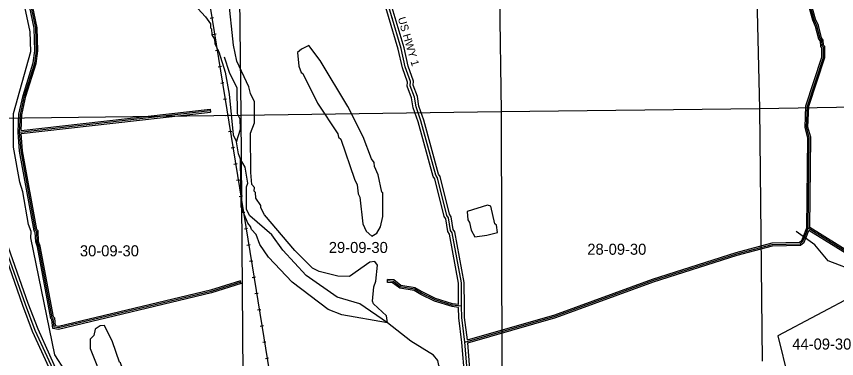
# Model space of a CAD drawing. Extents: x 418523 to 616617, y 1878279 to 2196743.
# Drawn here: x 553602 to 570344, y 1945489 to 1952469 of the extents above; entities that cross this region are included whole.
import ezdxf

# ---------------------------------------------------------------- set-up
doc = ezdxf.new("R2010")
doc.units = 0
for name, color, linetype in [('Level 1', 7, 'Continuous'), ('Level 13', 7, 'Continuous'), ('Level 14', 7, 'Continuous'), ('Level 19', 7, 'Continuous'), ('Level 2', 7, 'Continuous'), ('Level 31', 7, 'Continuous'), ('Level 32', 7, 'Continuous'), ('Level 34', 7, 'Continuous'), ('Level 37', 7, 'Continuous'), ('Level 5', 7, 'Continuous'), ('Level 7', 7, 'Continuous')]:
    doc.layers.add(name, color=color, linetype=linetype)

msp = doc.modelspace()

# ---------------------------------------------------------------- linework, layer by layer
at = {"layer": 'Level 1'}
for p, q in [((563413.668, 1955811.287), (563498.761, 1950526.305)), ((568644.303, 1955869.218), (568769.441, 1950592.162)), ((558122.982, 1955755.473), (558186.036, 1950452.524)), ((563498.761, 1950526.305), (568769.441, 1950592.162)), ((568769.441, 1950592.162), (573637.791, 1950674.806)), ((568769.441, 1950592.162), (568822.676, 1945437.311)), ((552971.413, 1950392.562), (558186.036, 1950452.524)), ((558186.036, 1950452.524), (563498.761, 1950526.305)), ((558186.036, 1950452.524), (558223.052, 1945139.621)), ((563498.761, 1950526.305), (563513.797, 1945243.459)), ((571579.462, 1947242.951), (569145.641, 1945954.963)), ((569145.641, 1945954.963), (571104.953, 1938088.985))]:
    msp.add_line(p, q, dxfattribs=at)
at = {"layer": 'Level 13'}
msp.add_line((562821.593, 1944999.369), (562756.996, 1945825.017), dxfattribs=at)
for points in [[(562689.623, 1946556.488), (562685.435, 1947033.971), (562496.226, 1948051.581), (562463.011, 1948101.485), (562422.072, 1948360.144), (562388.86, 1948410.412), (562199.028, 1949177.834), (562165.816, 1949227.738), (561860.66, 1950337.288), (561761.371, 1950621.189), (561728.546, 1950821.281), (561637.386, 1951054.979), (561645.854, 1951138.233), (561538.356, 1951438.521), (561456.135, 1951814.019), (561059.554, 1953157.276)], [(554472.45, 1945001.799), (553987.946, 1946065.361), (553789.032, 1946591.025), (553292.812, 1947992.826), (553284.471, 1948076.125), (553259.751, 1948092.921), (553243.201, 1948192.972), (553185.056, 1948293.139), (553143.949, 1948468.533), (553118.911, 1948485.331), (553011.661, 1948852.191), (552978.461, 1948902.468), (552912.389, 1949119.39), (552564.836, 1950070.586), (552399.28, 1950587.8), (552316.54, 1950746.585), (552184.116, 1951188.796), (552076.625, 1951464.019), (552043.066, 1951610.666)], [(562756.996, 1945825.017), (562691.579, 1946325.566), (562689.623, 1946556.488)]]:
    msp.add_lwpolyline(points, dxfattribs=at)
at = {"layer": 'Level 14'}
for p, q in [((562759.357, 1945025.605), (562697.3, 1945818.785)), ((562881.308, 1945005.39), (562818.249, 1945811.365))]:
    msp.add_line(p, q, dxfattribs=at)
for points in [[(562629.292, 1946593.916), (562625.482, 1947028.18), (562439.477, 1948028.55), (562405.797, 1948079.155), (562364.842, 1948337.919), (562333.097, 1948385.966), (562143.291, 1949153.286), (562110.521, 1949202.526), (561803.348, 1950319.407), (561703.008, 1950606.316), (561670.356, 1950805.348), (561576.228, 1951046.654), (561584.786, 1951130.796), (561480.567, 1951421.924), (561397.981, 1951799.088), (561001.794, 1953141.016)], [(562749.622, 1946557.015), (562745.388, 1947039.763), (562552.973, 1948074.611), (562520.226, 1948123.814), (562479.303, 1948382.37), (562444.622, 1948434.86), (562254.766, 1949202.381), (562221.111, 1949252.951), (561917.972, 1950355.168), (561819.735, 1950636.062), (561786.735, 1950837.214), (561698.544, 1951063.303), (561706.921, 1951145.671), (561596.145, 1951455.116), (561514.288, 1951828.951), (561130.681, 1953128.266)], [(554419.556, 1944973.172), (553932.526, 1946042.281), (553732.686, 1946570.393), (553233.831, 1947979.636), (553227.561, 1948042.251), (553204.752, 1948057.75), (553185.796, 1948172.346), (553128.676, 1948270.746), (553090.917, 1948431.858), (553067.424, 1948447.62), (552956.608, 1948826.675), (552923.598, 1948876.664), (552855.469, 1949100.337), (552508.061, 1950051.136), (552343.699, 1950564.622), (552260.696, 1950723.912), (552127.337, 1951169.242), (552019.123, 1951446.316), (551984.577, 1951597.281)], [(554525.345, 1945030.423), (554043.366, 1946088.441), (553845.379, 1946611.656), (553351.792, 1948006.015), (553341.381, 1948109.998), (553314.749, 1948128.093), (553300.606, 1948213.598), (553241.435, 1948315.531), (553196.981, 1948505.208), (553170.4, 1948523.041), (553066.715, 1948877.707), (553033.325, 1948928.271), (552969.31, 1949138.441), (552621.61, 1950090.036), (552454.861, 1950610.978), (552372.384, 1950769.258), (552240.895, 1951208.348), (552134.126, 1951481.721), (552098.567, 1951637.115)], [(562697.299, 1945818.785), (562631.611, 1946321.409), (562629.816, 1946533.426)], [(562811.392, 1945871.818), (562751.547, 1946329.722), (562749.622, 1946556.996)]]:
    msp.add_lwpolyline(points, dxfattribs=at)
at = {"layer": 'Level 31'}
for p, q in [((553665.121, 1950109.33), (557559.618, 1950548.909)), ((569686.732, 1947955.842), (569765.931, 1948148.755))]:
    msp.add_line(p, q, dxfattribs=at)
for points in [[(569765.931, 1948148.755), (569787.408, 1949999.317), (569729.792, 1950207.823), (569747.635, 1950641.252), (570075.391, 1951632.524), (570075.877, 1951840.894), (570050.854, 1951866.044), (570042.852, 1951974.431), (570009.613, 1952016.328), (569943.543, 1952274.674), (569885.735, 1952399.905), (569745.346, 1952917.344), (569679.006, 1953058.959), (569662.771, 1953175.729), (569612.826, 1953267.85), (569563.49, 1953484.701), (569513.523, 1953568.095), (569389.716, 1953976.766)], [(553665.121, 1950109.33), (553682.946, 1950467.841), (553767.196, 1950850.895), (553977.326, 1951517.25), (554011.356, 1951767.347), (553996.139, 1952234.318), (553757.382, 1953376.847), (553757.683, 1953485.215), (553732.672, 1953510.376), (553675.183, 1953844.005)], [(558183.743, 1947046.016), (557574.517, 1946855.996), (554463.129, 1946113.868), (554371.405, 1946130.849), (554355.353, 1946297.809), (554330.336, 1946322.97), (554059.041, 1947773.96), (554025.977, 1947874.056), (554018.298, 1948082.449), (553993.283, 1948107.61), (553697.395, 1949725.587), (553665.121, 1950109.33)], [(571714.751, 1946553.279), (571703.988, 1946567.85), (571130.54, 1947269.918), (570897.876, 1947445.37), (569765.931, 1948148.755)], [(562756.996, 1945825.017), (564600.716, 1946353.507), (566595.061, 1947081.73), (568305.656, 1947627.456), (569031.346, 1947817.379), (569598.171, 1947832.409), (569656.712, 1947882.456), (569686.732, 1947955.842)], [(562689.623, 1946556.488), (562500.109, 1946579.151), (562149.187, 1946688.411), (561871.686, 1946823.67), (561734.398, 1946904.388), (561438.581, 1946954.603), (561292.797, 1947064.8), (561178.502, 1947072.003)]]:
    msp.add_lwpolyline(points, dxfattribs=at)
at = {"layer": 'Level 32'}
for p, q in [((553696.839, 1950143.1), (557556.253, 1950578.72)), ((557556.253, 1950578.72), (557562.984, 1950519.097)), ((553697.461, 1950082.787), (557562.984, 1950519.097)), ((569658.98, 1947967.236), (569736, 1948154.84)), ((569714.486, 1947944.448), (569780.217, 1948104.556)), ((558192.676, 1947017.376), (558174.81, 1947074.656)), ((561176.615, 1947042.061), (561180.389, 1947101.945))]:
    msp.add_line(p, q, dxfattribs=at)
for points in [[(569736, 1948154.84), (569757.36, 1949995.42), (569699.623, 1950204.362), (569717.833, 1950646.683), (570045.401, 1951637.389), (570045.847, 1951828.541), (570021.752, 1951852.758), (570013.612, 1951963.016), (569982.134, 1952002.696), (569915.156, 1952264.587), (569857.441, 1952389.618), (569717.074, 1952906.975), (569649.916, 1953050.337), (569633.806, 1953166.211), (569584.486, 1953257.175), (569535.297, 1953473.383), (569485.885, 1953555.852), (569367.412, 1953946.916)], [(569796.126, 1948165.312), (569817.456, 1950003.216), (569759.961, 1950211.285), (569777.437, 1950635.821), (570105.38, 1951627.658), (570105.906, 1951853.246), (570079.955, 1951879.33), (570072.091, 1951985.845), (570037.093, 1952029.96), (569971.93, 1952284.761), (569914.03, 1952410.191), (569773.619, 1952927.713), (569708.097, 1953067.581), (569691.736, 1953185.247), (569641.164, 1953278.525), (569591.681, 1953496.019), (569541.161, 1953580.337), (569429.798, 1953947.933)], [(553635.059, 1950108.814), (553653.106, 1950471.836), (553738.183, 1950858.644), (553947.945, 1951523.831), (553981.289, 1951768.892), (553966.239, 1952230.735), (553727.373, 1953373.787), (553727.649, 1953472.875), (553704.716, 1953495.945), (553645.68, 1953838.554)], [(553696.839, 1950143.1), (553712.785, 1950463.846), (553796.21, 1950843.146), (554006.707, 1951510.668), (554041.422, 1951765.803), (554026.039, 1952237.902), (553787.391, 1953379.906), (553787.718, 1953497.555), (553760.629, 1953524.806), (553709.216, 1953823.171)], [(558192.676, 1947017.376), (557582.473, 1946827.051), (554463.911, 1946083.212), (554343.706, 1946105.466), (554326.516, 1946284.262), (554302.546, 1946308.371), (554029.922, 1947766.464), (553996.154, 1947868.692), (553988.75, 1948069.618), (553965.446, 1948093.058), (553667.621, 1949721.623), (553635.059, 1950108.814)], [(558174.81, 1947074.656), (557566.561, 1946884.94), (554462.346, 1946144.524), (554399.103, 1946156.231), (554384.189, 1946311.355), (554358.128, 1946337.568), (554088.16, 1947781.455), (554055.8, 1947879.419), (554047.846, 1948095.28), (554021.12, 1948122.161), (553727.168, 1949729.552), (553697.461, 1950082.787)], [(571690.479, 1946535.646), (571680.291, 1946549.437), (571109.591, 1947248.141), (570880.892, 1947420.602), (569780.217, 1948104.556)], [(571732.112, 1946580.268), (571727.685, 1946586.262), (571151.488, 1947291.696), (570914.859, 1947470.137), (569796.127, 1948165.312)], [(562811.391, 1945871.818), (564591.426, 1946382.053), (566585.352, 1947110.123), (568297.292, 1947656.279), (569027.094, 1947847.277), (569586.753, 1947862.118), (569631.696, 1947900.538), (569658.965, 1947967.201)], [(562818.25, 1945811.366), (564610.006, 1946324.961), (566604.769, 1947053.337), (568314.019, 1947598.634), (569035.596, 1947787.481), (569609.587, 1947802.701), (569681.729, 1947864.373), (569714.5, 1947944.485)], [(562629.292, 1946593.916), (562506.402, 1946608.613), (562160.281, 1946716.377), (561885.882, 1946850.125), (561744.853, 1946933.043), (561450.826, 1946982.955), (561303.69, 1947094.173), (561180.389, 1947101.945)], [(562629.816, 1946533.426), (562493.816, 1946549.69), (562138.092, 1946660.444), (561857.489, 1946797.215), (561723.943, 1946875.733), (561426.336, 1946926.251), (561281.905, 1947035.426), (561176.615, 1947042.061)]]:
    msp.add_lwpolyline(points, dxfattribs=at)
at = {"layer": 'Level 37'}
for p, q in [((557558.192, 1952432.732), (557624.666, 1952443.513)), ((557611.803, 1952102.19), (557678.278, 1952112.971)), ((557665.415, 1951771.647), (557731.889, 1951782.429)), ((557719.033, 1951441.105), (557785.506, 1951451.888)), ((557772.657, 1951110.565), (557839.131, 1951121.349)), ((557826.282, 1950780.024), (557892.756, 1950790.808)), ((557879.906, 1950449.483), (557946.381, 1950460.268)), ((557933.531, 1950118.944), (558000.005, 1950129.727)), ((557987.156, 1949788.403), (558053.629, 1949799.188)), ((558040.78, 1949457.863), (558107.254, 1949468.647)), ((558094.404, 1949127.322), (558160.879, 1949138.107)), ((558148.03, 1948796.783), (558214.503, 1948807.566)), ((558201.654, 1948466.242), (558268.127, 1948477.027)), ((558255.278, 1948135.702), (558321.752, 1948146.486)), ((558308.902, 1947805.161), (558375.376, 1947815.946)), ((558362.526, 1947474.622), (558429.001, 1947485.406)), ((558416.152, 1947144.081), (558482.626, 1947154.866)), ((558469.786, 1946813.542), (558536.259, 1946824.328)), ((558523.421, 1946483.003), (558589.895, 1946493.789)), ((558577.055, 1946152.464), (558643.529, 1946163.251)), ((558630.69, 1945821.926), (558697.163, 1945832.712)), ((558684.324, 1945491.387), (558750.798, 1945502.174))]:
    msp.add_line(p, q, dxfattribs=at)
msp.add_lwpolyline([(554866.266, 1969249.629), (554867.125, 1969244.323), (555789.684, 1963551.706), (557100.687, 1955463.798), (557725.337, 1951612.51), (558452.601, 1947129.67), (559310.996, 1941839.571), (559435.7, 1941071.581), (559469.888, 1940786.39), (559492.892, 1940596.141), (560291.277, 1935684.071), (560315.664, 1935534.186)], dxfattribs=at)
at = {"layer": 'Level 5'}
for points in [[(554493.166, 1944447.941), (554302.696, 1944848.678), (554344.616, 1944923.57), (554628.639, 1945097.758), (554595.716, 1945239.571), (554388.346, 1945565.346), (553895.851, 1947951.146), (553904.609, 1948084.489), (553846.716, 1948226.401), (553732.123, 1948893.676), (553674.389, 1949085.61), (553543.295, 1949802.955), (553545.515, 1950486.541), (553899.694, 1951752.556), (553884.298, 1952152.735), (553654.376, 1953245.547), (553327.001, 1955130.638), (553113.451, 1956131.688), (552748.782, 1956799.78), (552607.746, 1957008.642), (552591.265, 1957075.364), (552309.331, 1957543.121), (552201.775, 1957793.566), (552086.446, 1958227.414)], [(558095.336, 1949913.398), (558179.544, 1950171.555), (558171.831, 1950371.66), (558113.838, 1950480.201), (558107.171, 1951005.424), (557949.822, 1951322.729), (557850.796, 1951639.836)], [(558177.553, 1949554.671), (558136.231, 1949663.172), (558095.336, 1949913.398)], [(561176.289, 1946218.821), (560610.661, 1946604.093), (560152.588, 1946738.94), (559520.428, 1947182.832), (559038.59, 1947701.218), (558814.49, 1948010.382), (558365.604, 1948403.626), (558299.301, 1948528.908), (558300.804, 1948995.739), (558326.074, 1949070.671), (558268.737, 1949395.988), (558177.553, 1949554.671)], [(570774.829, 1947255.053), (570175.332, 1947482.061), (569901.271, 1947808.065), (569518.689, 1948084.406)], [(564128.021, 1938623.19), (564103.867, 1938890.046), (564054.075, 1938965.236), (563872.244, 1939449.336), (563806.897, 1939866.355), (563600.026, 1940342.173), (563501.258, 1940742.651), (563418.583, 1940959.656), (563204.287, 1941718.981), (562988.528, 1942028.116), (562947.166, 1942128.287), (562914.971, 1942486.846), (562873.677, 1942612.018), (562541.535, 1943013.243), (562559.41, 1943396.652), (562669.156, 1943821.484), (562654.019, 1944296.685), (562522.269, 1944805.626), (562223.894, 1945348.474), (562207.552, 1945448.536), (562116.179, 1945557.208), (561650.255, 1945842.148), (561176.289, 1946218.821)]]:
    msp.add_lwpolyline(points, dxfattribs=at)
for points in [[(562957.583, 1947972.066), (563207.779, 1948004.631), (563424.722, 1948062.265), (563400.17, 1948212.418), (563366.919, 1948237.528), (563284.702, 1948596.256), (563218.07, 1948621.485), (562800.832, 1948489.446), (562816.986, 1948322.653), (562850.127, 1948264.201), (562882.99, 1948105.718), (562957.583, 1947972.066)], [(555486.133, 1944744.851), (555895.17, 1944918.601), (555730.009, 1945402.64), (555705.038, 1945419.41), (555564.659, 1945828.347), (555398.981, 1946162.323), (555315.579, 1946154.252), (555207.007, 1946087.919), (555181.609, 1945962.936), (555106.318, 1945888.173), (555105.701, 1945696.438), (555246.339, 1945354.192), (555254.451, 1945279.131), (555436.511, 1944861.723), (555436.281, 1944795.031), (555486.133, 1944744.851)]]:
    msp.add_lwpolyline(points, close=True, dxfattribs=at)
at = {"layer": 'Level 7'}
for points in [[(557154.243, 1952792.473), (557461.605, 1952458.04), (557561.179, 1952315.997), (557560.921, 1952232.636), (557585.861, 1952215.896), (557593.813, 1952090.813), (557643.566, 1952007.291), (557651.577, 1951907.219), (557734.421, 1951748.566), (557866.461, 1951331.328), (557948.389, 1950880.899), (558029.102, 1950055.341), (558095.336, 1949913.398)], [(561176.289, 1946218.821), (561160.076, 1946360.574), (560894.096, 1946603.206), (560869.256, 1946661.627), (560895.211, 1946953.335), (560937.281, 1947069.878), (560971.677, 1947394.896), (560921.885, 1947470.087), (560813.443, 1947453.776), (560404.048, 1947163.313), (560162.332, 1947172.431), (559779.152, 1947265.337), (559645.968, 1947332.457), (559288.645, 1947692.061), (558665.771, 1948419.35), (558591.207, 1948561.302), (558591.336, 1948611.324), (558491.791, 1948761.706), (558483.84, 1948878.438), (558458.899, 1948903.519), (558459.128, 1948978.541), (558409.306, 1949037.061), (558385.111, 1949287.246), (558379.33, 1950087.546), (558463.379, 1950295.691), (558464.752, 1950729.182), (558381.938, 1950896.165), (558349.016, 1951029.647), (558100.592, 1951555.656), (558034.946, 1951880.974), (557929.72, 1952856.686)], [(561176.289, 1946218.821), (560243.146, 1946380.182), (559968.368, 1946489.441), (559228.233, 1947050.365), (558746.355, 1947560.451), (558572.147, 1947819.435), (558497.742, 1948019.728), (558398.029, 1948120.1), (558381.587, 1948186.851), (558323.426, 1948253.701), (558191.127, 1948587.588), (558177.553, 1949554.671)]]:
    msp.add_lwpolyline(points, dxfattribs=at)
msp.add_lwpolyline([(560856.856, 1947987.169), (560957.057, 1948045.201), (561032.517, 1948178.326), (561083.216, 1948386.571), (561084.749, 1948870.073), (561059.808, 1948886.843), (560985.891, 1949237.2), (560911.417, 1949404.153), (560903.346, 1949487.555), (560853.553, 1949562.746), (560679.963, 1950013.465), (560365.147, 1950631.365), (559801.281, 1951566.87), (559568.841, 1951876.064), (559418.559, 1951801.53), (559343.298, 1951735.067), (559367.422, 1951451.571), (559417.016, 1951326.359), (559450.296, 1951301.219), (559748.482, 1950700.048), (560163.271, 1950073.489), (560179.751, 1950006.728), (560221.303, 1949964.917), (560502.091, 1949147.071), (560560.085, 1949030.17), (560576.167, 1948846.696), (560609.289, 1948779.914), (560674.248, 1948237.852), (560740.442, 1948087.57), (560856.856, 1947987.169)], close=True, dxfattribs=at)

# ---------------------------------------------------------------- texts
at = {"layer": 'Level 19'}
msp.add_text('US HWY 1', height=160, rotation=286.4478333, dxfattribs=at).set_placement((561385.337, 1952431.521))
at = {"layer": 'Level 2'}
for s, p in [('30-09-30', (554898.558, 1947575.246)), ('29-09-30', (559978.984, 1947643.177)), ('28-09-30', (565255.622, 1947607.264)), ('44-09-30', (569439.723, 1945672.893))]:
    msp.add_text(s, height=225, dxfattribs=at).set_placement(p)
at = {"layer": 'Level 34'}
for rotation, p in [(286.4478333, (561224.186, 1952555.512)), (277.445075, (562701.975, 1946149.563))]:
    msp.add_text('US HWY 1', height=25, rotation=rotation, dxfattribs=at).set_placement(p)

doc.saveas('drawing.dxf')
